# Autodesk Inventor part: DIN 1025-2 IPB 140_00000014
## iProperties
Created: 2006-02
Part Number: DIN 1025-2 IPB 140_00000014
Material: Default
Document SubType Name: Modeling
Designer: 40664
Manufacturer: Standard
Standards Organization: Custom
Stock Number: DIN 1025-2 IPB 140
Mass: 11082.7 g
Surface Area: 20865.2 cm^2
Volume: 11082.7 cm^3
Density: 1 g/cm^3
G_L: 2580.000 mm
G_W: 140.000 mm
G_H: 140.000 mm
AFG_Item: IPB 140
CSToolsMass: 11.0
CSToolsVolume: 11082691.0
CSToolsArea: 20865.0
Author: 40664
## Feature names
1. AFG_Detailed_DIN 1025-2 IPB 140_00000014 [Extrusion]
2. AFG_Simplified_DIN 1025-2 IPB 140_00000014 [Extrusion]
